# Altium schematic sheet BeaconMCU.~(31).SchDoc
size A4
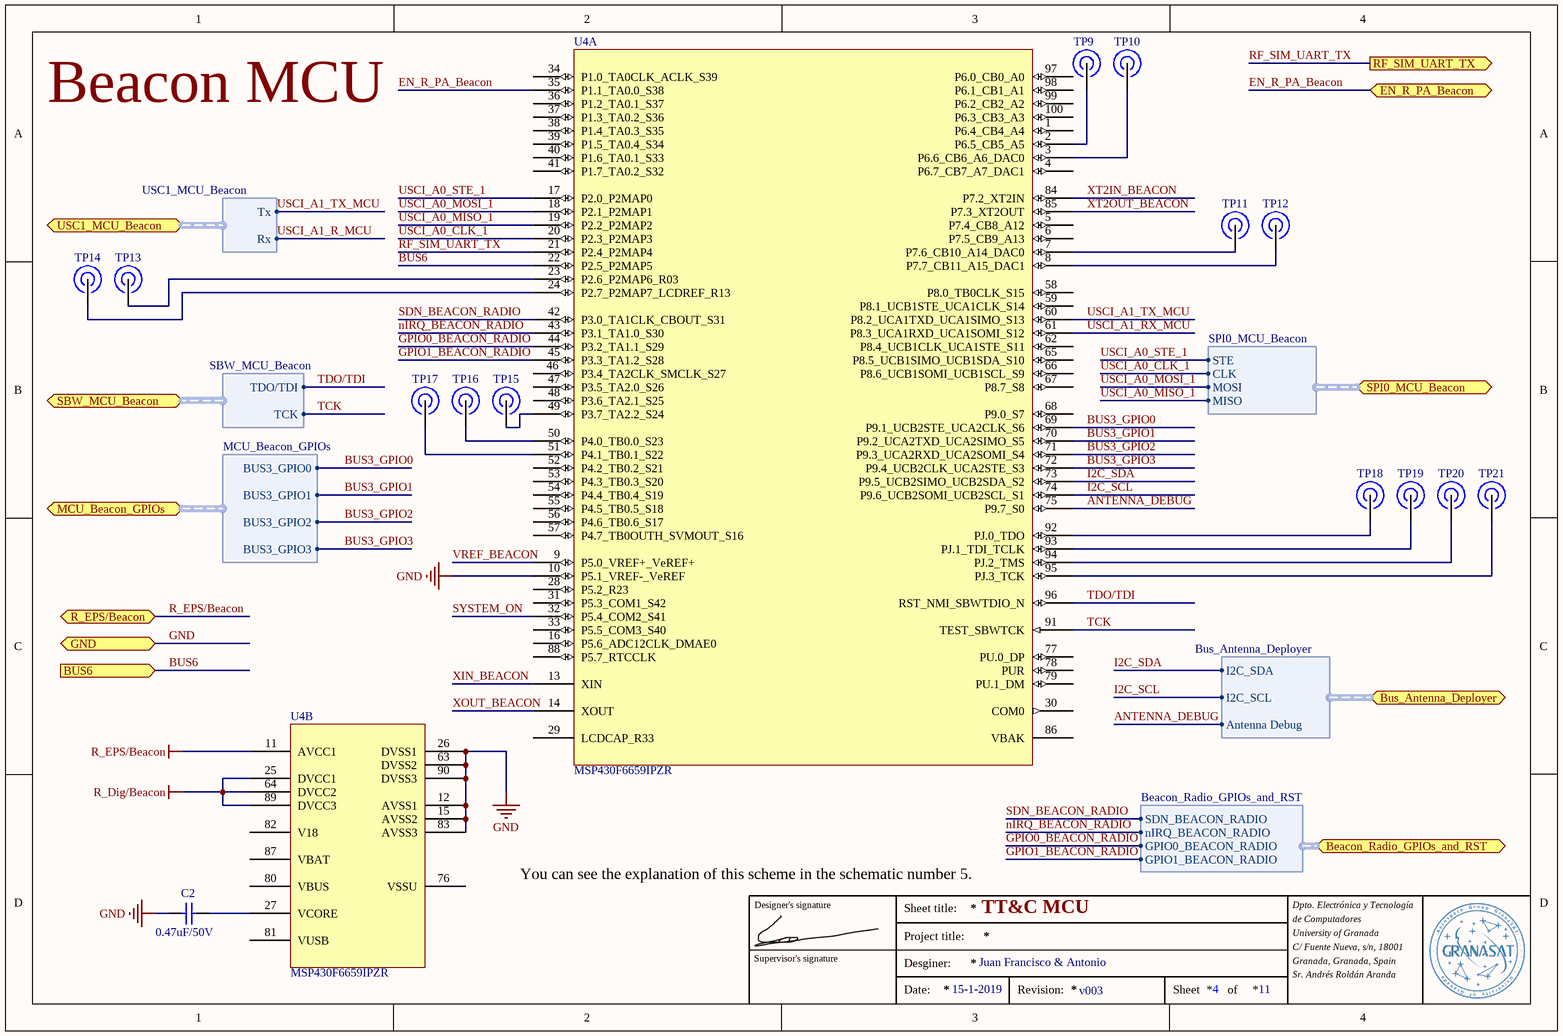
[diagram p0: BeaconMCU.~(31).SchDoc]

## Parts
C2  value 0.47uF/50V  [C0.47u]
TP9  TestPoint  [TESTPOINT_2x2mm]  (value not drawn)
TP10  TestPoint  [TESTPOINT_2x2mm]  (value not drawn)
TP11  TestPoint  [TESTPOINT_2x2mm]  (value not drawn)
TP12  TestPoint  [TESTPOINT_2x2mm]  (value not drawn)
TP13  TestPoint  [TESTPOINT_2x2mm]  (value not drawn)
TP14  TestPoint  [TESTPOINT_2x2mm]  (value not drawn)
TP15  TestPoint  [TESTPOINT_2x2mm]  (value not drawn)
TP16  TestPoint  [TESTPOINT_2x2mm]  (value not drawn)
TP17  TestPoint  [TESTPOINT_2x2mm]  (value not drawn)
TP18  TestPoint  [TESTPOINT_2x2mm]  (value not drawn)
TP19  TestPoint  [TESTPOINT_2x2mm]  (value not drawn)
TP20  TestPoint  [TESTPOINT_2x2mm]  (value not drawn)
TP21  TestPoint  [TESTPOINT_2x2mm]  (value not drawn)
U4A  MSP430F6659IPZR  [MSP430F6659IPZR]
U4B  MSP430F6659IPZR  [MSP430F6659IPZR]

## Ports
Beacon_Radio_GPIOs_and_RST (harness Beacon_Radio_GPIOs_and_RST), BUS6 (in), Bus_Antenna_Deployer (harness Bus_Antenna_Deployer), EN_R_PA_Beacon, GND, MCU_Beacon_GPIOs (harness MCU_Beacon_GPIOs), R_EPS/Beacon (bidir), RF_SIM_UART_TX (out), SBW_MCU_Beacon (harness SBW_MCU_Beacon), SPI0_MCU_Beacon (harness SPI0_MCU_Beacon), USC1_MCU_Beacon (harness USC1_MCU_Beacon)

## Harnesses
USC1_MCU_Beacon: Rx, Tx
SBW_MCU_Beacon: TCK, TDO/TDI
MCU_Beacon_GPIOs: BUS3_GPIO0, BUS3_GPIO1, BUS3_GPIO2, BUS3_GPIO3
Bus_Antenna_Deployer: I2C_SDA, I2C_SCL, Antenna Debug
Beacon_Radio_GPIOs_and_RST: SDN_BEACON_RADIO, nIRQ_BEACON_RADIO, GPIO0_BEACON_RADIO, GPIO1_BEACON_RADIO
SPI0_MCU_Beacon: STE, CLK, MOSI, MISO

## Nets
GND: C2.1 U4A.10(P5.1_VREF-_VeREF) U4B.12(AVSS1) U4B.15(AVSS2) U4B.26(DVSS1) U4B.63(DVSS2) U4B.83(AVSS3) U4B.90(DVSS3) ; port GND
R_Dig/Beacon: U4B.25(DVCC1) U4B.64(DVCC2) U4B.89(DVCC3)
R_EPS/Beacon: U4B.11(AVCC1) ; port R_EPS/Beacon
ANTENNA_DEBUG: U4A.75(P9.7_S0) ; port Bus_Antenna_Deployer.Antenna Debug
BUS3_GPIO0: U4A.69(P9.1_UCB2STE_UCA2CLK_S6) ; port MCU_Beacon_GPIOs.BUS3_GPIO0
BUS3_GPIO1: U4A.70(P9.2_UCA2TXD_UCA2SIMO_S5) ; port MCU_Beacon_GPIOs.BUS3_GPIO1
BUS3_GPIO2: U4A.71(P9.3_UCA2RXD_UCA2SOMI_S4) ; port MCU_Beacon_GPIOs.BUS3_GPIO2
BUS3_GPIO3: U4A.72(P9.4_UCB2CLK_UCA2STE_S3) ; port MCU_Beacon_GPIOs.BUS3_GPIO3
BUS6: U4A.22(P2.5_P2MAP5) ; port BUS6
EN_R_PA_Beacon: U4A.35(P1.1_TA0.0_S38) ; port EN_R_PA_Beacon
GPIO0_BEACON_RADIO: U4A.44(P3.2_TA1.1_S29) ; port Beacon_Radio_GPIOs_and_RST.GPIO0_BEACON_RADIO
GPIO1_BEACON_RADIO: U4A.45(P3.3_TA1.2_S28) ; port Beacon_Radio_GPIOs_and_RST.GPIO1_BEACON_RADIO
I2C_SCL: U4A.74(P9.6_UCB2SOMI_UCB2SCL_S1) ; port Bus_Antenna_Deployer.I2C_SCL
I2C_SDA: U4A.73(P9.5_UCB2SIMO_UCB2SDA_S2) ; port Bus_Antenna_Deployer.I2C_SDA
nIRQ_BEACON_RADIO: U4A.43(P3.1_TA1.0_S30) ; port Beacon_Radio_GPIOs_and_RST.nIRQ_BEACON_RADIO
RF_SIM_UART_TX: U4A.21(P2.4_P2MAP4) ; port RF_SIM_UART_TX
SDN_BEACON_RADIO: U4A.42(P3.0_TA1CLK_CBOUT_S31) ; port Beacon_Radio_GPIOs_and_RST.SDN_BEACON_RADIO
SYSTEM_ON: U4A.32(P5.4_COM2_S41)
TCK: U4A.91(TEST_SBWTCK) ; port SBW_MCU_Beacon.TCK
TDO/TDI: U4A.96(RST_NMI_SBWTDIO_N) ; port SBW_MCU_Beacon.TDO/TDI
USCI_A0_CLK_1: U4A.20(P2.3_P2MAP3) ; port SPI0_MCU_Beacon.CLK
USCI_A0_MISO_1: U4A.19(P2.2_P2MAP2) ; port SPI0_MCU_Beacon.MISO
USCI_A0_MOSI_1: U4A.18(P2.1_P2MAP1) ; port SPI0_MCU_Beacon.MOSI
USCI_A0_STE_1: U4A.17(P2.0_P2MAP0) ; port SPI0_MCU_Beacon.STE
USCI_A1_RX_MCU: U4A.61(P8.3_UCA1RXD_UCA1SOMI_S12)
USCI_A1_TX_MCU: U4A.60(P8.2_UCA1TXD_UCA1SIMO_S13) ; port USC1_MCU_Beacon.Tx
VREF_BEACON: U4A.9(P5.0_VREF+_VeREF+)
XIN_BEACON: U4A.13(XIN)
XOUT_BEACON: U4A.14(XOUT)
XT2IN_BEACON: U4A.84(P7.2_XT2IN)
XT2OUT_BEACON: U4A.85(P7.3_XT2OUT)
NetC2_2: C2.2 U4B.27(VCORE)
NetTP9_1: TP9.1 U4A.2(P6.5_CB5_A5)
NetTP10_1: TP10.1 U4A.3(P6.6_CB6_A6_DAC0)
NetTP11_1: TP11.1 U4A.7(P7.6_CB10_A14_DAC0)
NetTP12_1: TP12.1 U4A.8(P7.7_CB11_A15_DAC1)
NetTP13_1: TP13.1 U4A.23(P2.6_P2MAP6_R03)
NetTP14_1: TP14.1 U4A.24(P2.7_P2MAP7_LCDREF_R13)
NetTP15_1: TP15.1 U4A.49(P3.7_TA2.2_S24)
NetTP16_1: TP16.1 U4A.50(P4.0_TB0.0_S23)
NetTP17_1: TP17.1 U4A.51(P4.1_TB0.1_S22)
NetTP18_1: TP18.1 U4A.92(PJ.0_TDO)
NetTP19_1: TP19.1 U4A.93(PJ.1_TDI_TCLK)
NetTP20_1: TP20.1 U4A.94(PJ.2_TMS)
NetTP21_1: TP21.1 U4A.95(PJ.3_TCK)

Not connected (* = marked no-connect by the designer): U4A 1(P6.4_CB4_A4) 4(P6.7_CB7_A7_DAC1) 5(P7.4_CB8_A12) 6(P7.5_CB9_A13) 16(P5.6_ADC12CLK_DMAE0) 28(P5.2_R23) 29(LCDCAP_R33) 30(COM0) 31(P5.3_COM1_S42) 33(P5.5_COM3_S40) 34(P1.0_TA0CLK_ACLK_S39) 36(P1.2_TA0.1_S37) 37(P1.3_TA0.2_S36) 38(P1.4_TA0.3_S35) 39(P1.5_TA0.4_S34) 40(P1.6_TA0.1_S33) 41(P1.7_TA0.2_S32) 46(P3.4_TA2CLK_SMCLK_S27) 47(P3.5_TA2.0_S26) 48(P3.6_TA2.1_S25) 52(P4.2_TB0.2_S21) 53(P4.3_TB0.3_S20) 54(P4.4_TB0.4_S19) 55(P4.5_TB0.5_S18) 56(P4.6_TB0.6_S17) 57(P4.7_TB0OUTH_SVMOUT_S16) 58(P8.0_TB0CLK_S15) 59(P8.1_UCB1STE_UCA1CLK_S14) 62(P8.4_UCB1CLK_UCA1STE_S11) 65(P8.5_UCB1SIMO_UCB1SDA_S10) 66(P8.6_UCB1SOMI_UCB1SCL_S9) 67(P8.7_S8) 68(P9.0_S7) 77(PU.0_DP) 78(PUR) 79(PU.1_DM) 86(VBAK) 88(P5.7_RTCCLK) 97(P6.0_CB0_A0) 98(P6.1_CB1_A1) 99(P6.2_CB2_A2) 100(P6.3_CB3_A3); U4B 76(VSSU) 80(VBUS) 81(VUSB) 82(V18) 87(VBAT)

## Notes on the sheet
- Beacon MCU
- Designer's signature
- Sheet title:
- TT&C MCU
- Dpto. Electrónica y Tecnología
- de Computadores
- You can see the explanation of this scheme in the schematic number 5.
- Supervisor's signature
- Project title:
- Desginer:
- Juan Francisco & Antonio
- University of Granada
- C/ Fuente Nueva, s/n, 18001
- Granada, Granada, Spain
- Sr. Andrés Roldán Aranda
- Date:
- 15-1-2019
- Revision:
- v003
- Sheet
- 4
- of
- 11

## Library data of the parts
C2 = Cap Semi: Capacitor (Semiconductor SIM Model)
TP9-TP21 = TestPoint: Punto de prueba de 3x3mm; pin to pad: 1>TP; PCB DECAL: TestPoint XxXmm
